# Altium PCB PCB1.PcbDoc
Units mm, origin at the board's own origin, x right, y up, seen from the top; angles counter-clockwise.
Board outline 100 x 70 mm, 2 copper layers (Top Layer, Bottom Layer); 90 components, 34 nets, 176 pads, 28 vias.
Unrouted connection lines stored in the file: 3.
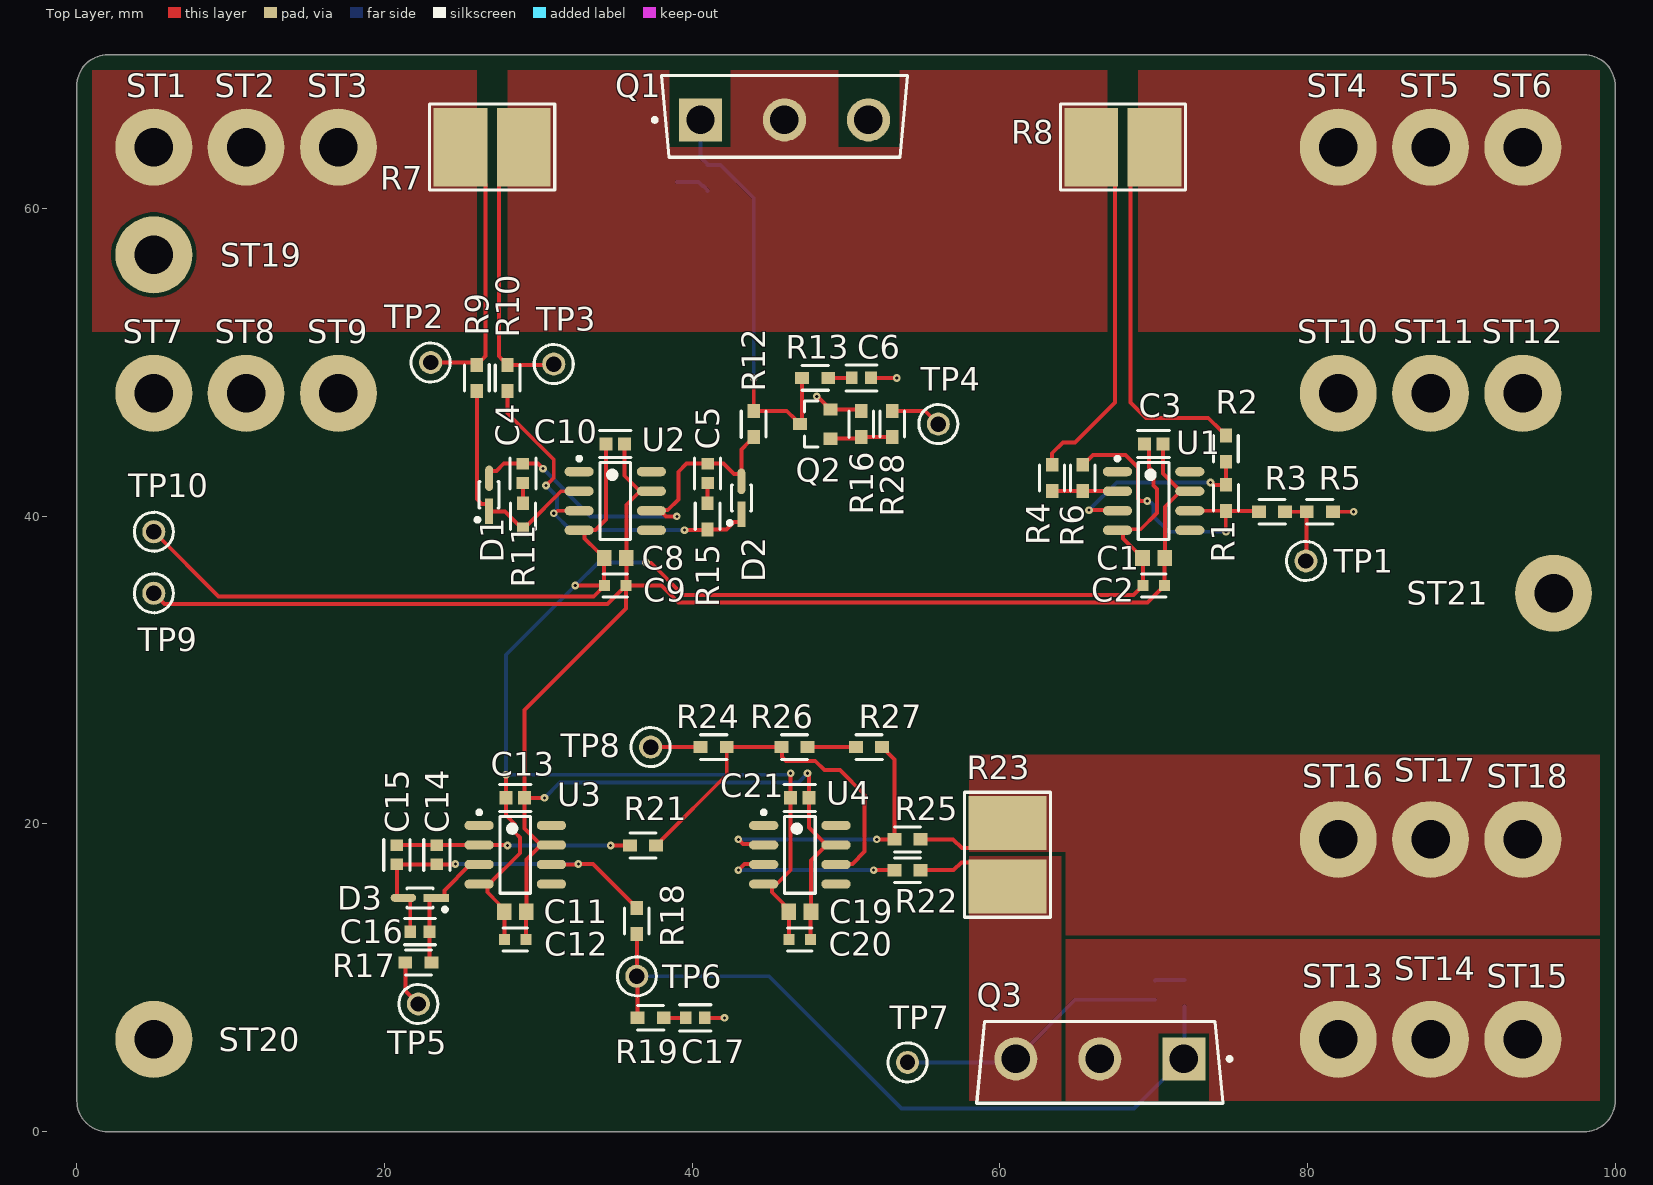
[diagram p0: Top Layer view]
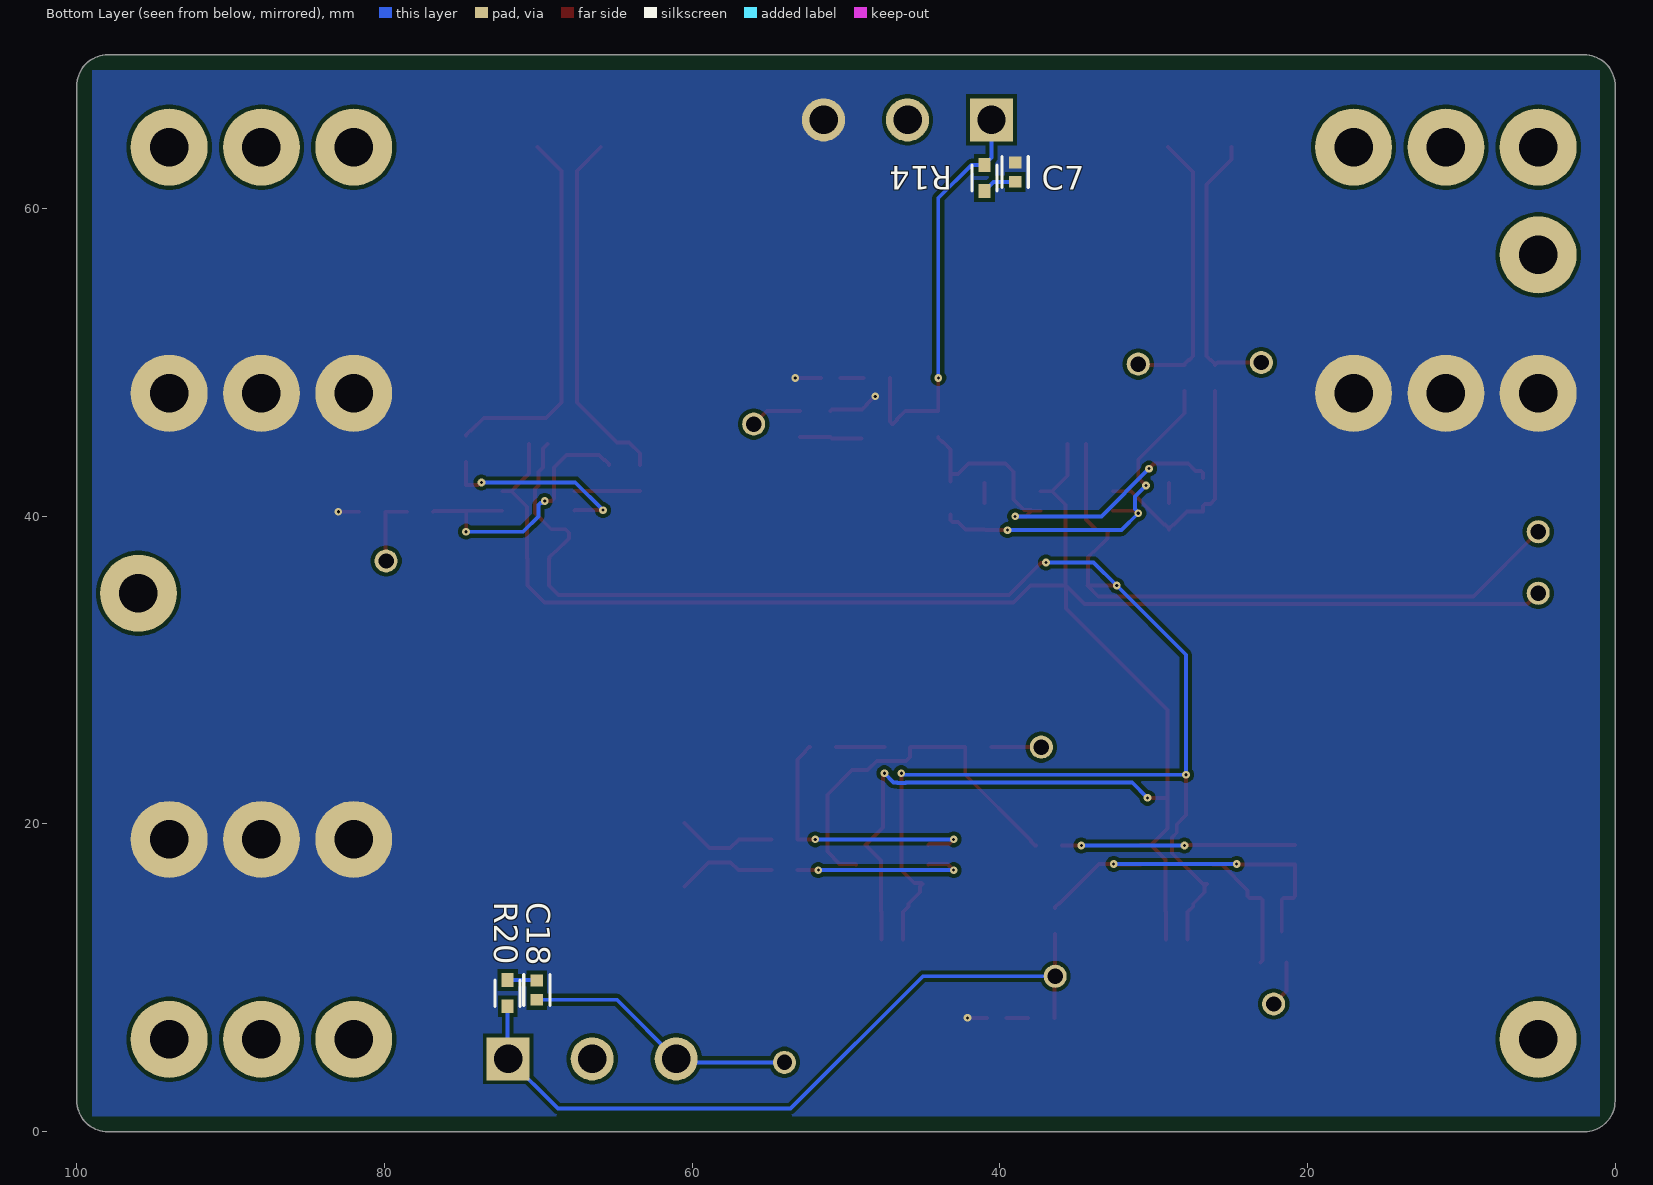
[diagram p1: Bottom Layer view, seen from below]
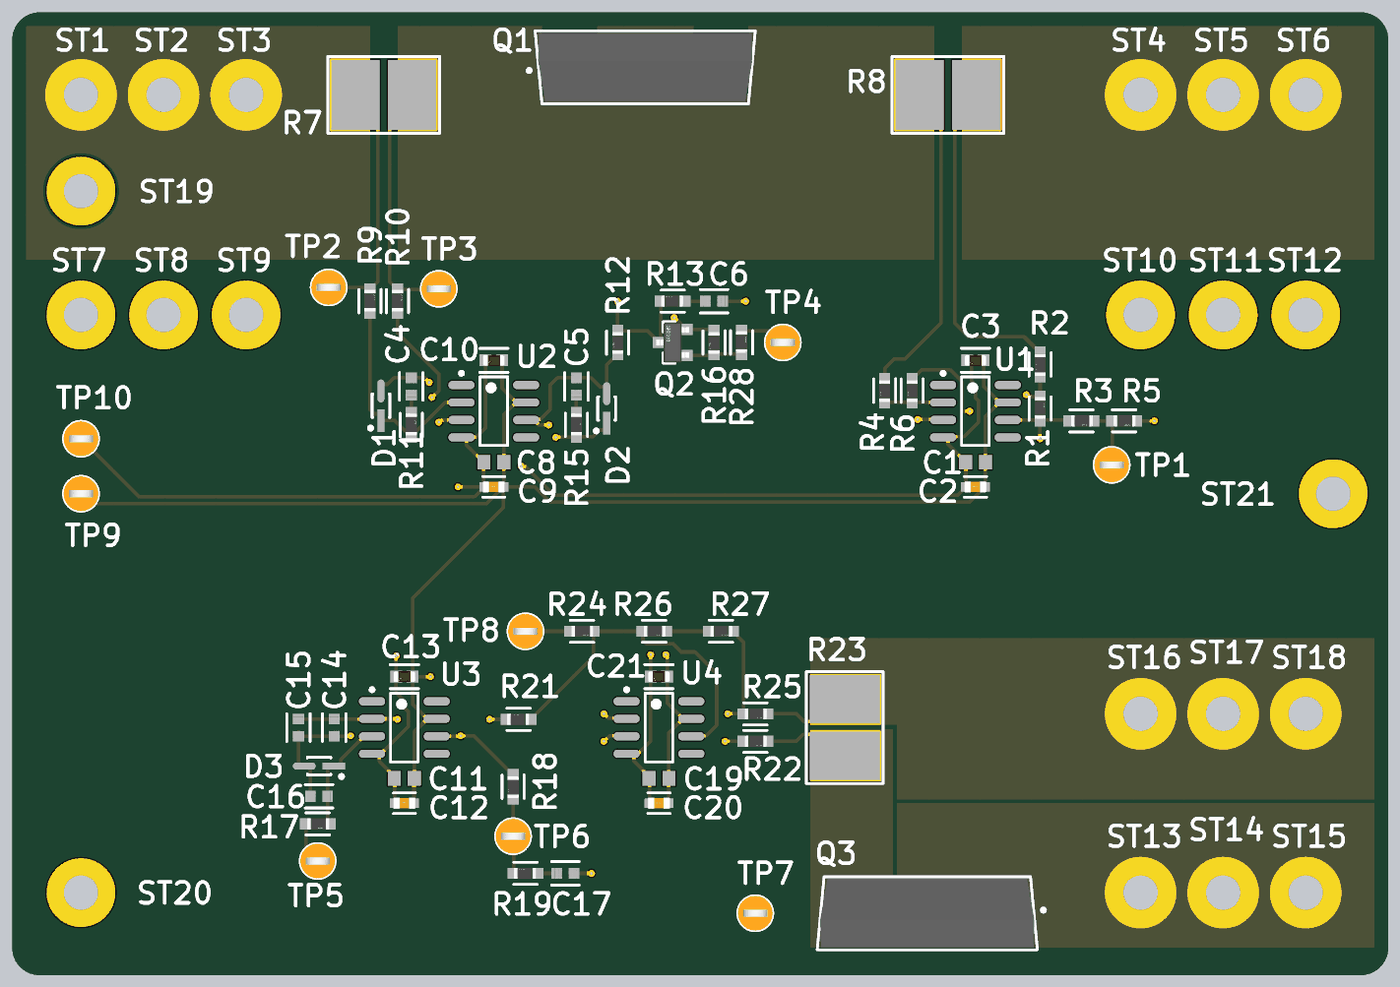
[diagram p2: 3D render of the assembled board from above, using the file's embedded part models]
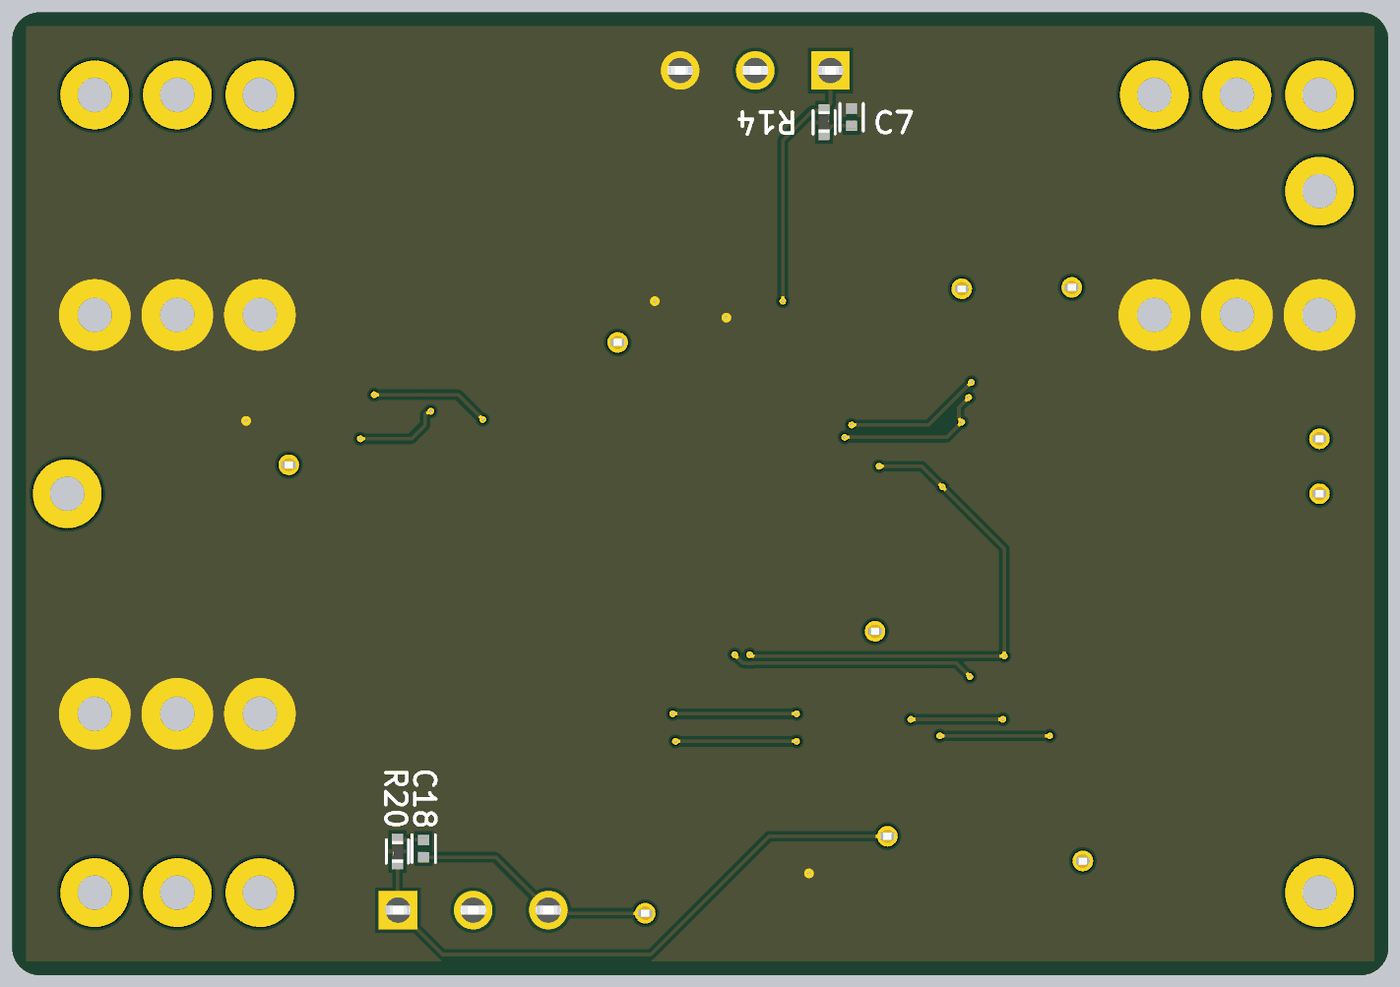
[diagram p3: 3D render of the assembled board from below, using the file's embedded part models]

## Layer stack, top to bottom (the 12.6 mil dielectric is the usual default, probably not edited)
Top Solder: solder mask 0.0102, Solder Resist, Dk 3.5
Top Layer: signal copper 0.0356
Dielectric 1: dielectric 0.32, FR-4, Dk 4.8
Bottom Layer: signal copper 0.0356
Bottom Solder: solder mask 0.0102, Solder Resist, Dk 3.5

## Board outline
2,0 98,0 ccw(c98,2) 100,2 100,68 ccw(c98,68) 98,70 2,70 ccw(c2,68) 0,68 0,2 ccw(c2,2)

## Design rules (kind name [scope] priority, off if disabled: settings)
Clearance [All] p1: gap=0.254 ignorepadtopadclearanceinfootprint=FALSE except(0: Arc-Hole Track-Hole SMDPad-Hole THPad-Hole Via-Hole Fill-Hole Poly-Hole Region-Hole Text-Hole)
PolygonConnect PolygonConnect_1 [All vs IsNamedPolygon('NONET_L01_P-001') Or IsNamedPolygon('NONET_L01_P-001') Or IsNamedPolygon('NONET_L01_P-001') Or IsNamedPolygon('NONET_L01_P-001') Or IsNamedPolygon('NONET_L01_P-001') Or IsNamedPolygon('NONET_L01_P-001') Or IsNamedPolygon('NONET_L01_P-001')] p1: connectstyle=Direct reliefconductorwidth=0.254 reliefentries=4 polygonreliefangle="90 Angle" airgapwidth=0.254
PolygonConnect [All] p2: connectstyle=Relief reliefconductorwidth=0.254 reliefentries=4 polygonreliefangle="90 Angle" airgapwidth=0.254
RoutingVias [All] p1: holewidth=0.2 width=0.5 viastyle="Through Hole" minholewidth=0.2 minwidth=0.5 maxholewidth=0.2 maxwidth=0.5
SilkToSilkClearance [All] p1: silktosilkclearance=0.15
SolderMaskExpansion [All] p1: expansion=0.102 istentingtop=FALSE
Width [All] p1: maxlimit=0.254 minlimit=0.254 preferedwidth=0.254
29 further rules are at their usual default settings.

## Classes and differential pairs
component class CV: C1 C2 C3 C4 C5 C6 C7 C8 C9 C10 D1 D2 Q1 Q2 R1 R2 R3 R4 R5 R6 R7 R8 R9 R10 R11 R12 R13 R14 R15 R16 R28 ST1 ST2 ST3 ST4 ST5 ST6 ST7 ST8 ST9 ST10 ST11 ST12 ST20 TP1 TP2 TP3 TP4 TP9 TP10 U1 U2
component class CC: C11 C12 C13 C14 C15 C16 C17 C18 C19 C20 C21 D3 Q3 R17 R18 R19 R20 R21 R22 R23 R24 R25 R26 R27 ST13 ST14 ST15 ST16 ST17 ST18 TP5 TP6 TP7 TP8 U3 U4

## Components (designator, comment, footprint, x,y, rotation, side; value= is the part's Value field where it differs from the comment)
C1 "CL10B104KB8NNNC" SAMS-C0603-2_M 70,37.3 r0 top
C2 "C1608X7R1H103M080AA" FP-C1608-080-0_1-MFG 70,35.5 r0 top
C3 "UMK107AB7105KA-T" FP-0603-L_1_6_0_15-W_0_8-IPC_C 70,44.7 r180 top
C4 "CL10B102KB8WPNC" FP-CL10-IPC_C 29,42.8 r90 top
C5 "CL10B102KB8WPNC" FP-CL10-IPC_C 41,42.8 r90 top
C6 "CL10B102KB8WPNC" FP-CL10-IPC_C 51,49 r180 top
C7 "CL10B102KB8WPNC" FP-CL10-IPC_C 39,62.373 r270 bottom
C8 "CL10B104KB8NNNC" SAMS-C0603-2_M 35,37.3 r0 top
C9 "C1608X7R1H103M080AA" FP-C1608-080-0_1-MFG 35,35.5 r0 top
C10 "UMK107AB7105KA-T" FP-0603-L_1_6_0_15-W_0_8-IPC_C 35,44.7 r180 top
C11 "CL10B104KB8NNNC" SAMS-C0603-2_M 28.5,14.3 r0 top
C12 "C1608X7R1H103M080AA" FP-C1608-080-0_1-MFG 28.5,12.5 r0 top
C13 "UMK107AB7105KA-T" FP-0603-L_1_6_0_15-W_0_8-IPC_C 28.5,21.7 r180 top
C14 "CL10B102KB8WPNC" FP-CL10-IPC_C 23.4,18 r90 top
C15 "CL10B102KB8WPNC" FP-CL10-IPC_C 20.8,18 r90 top
C16 "CL10B102KB8WPNC" FP-CL10-IPC_C 22.3,13 r0 top
C17 "CL10B102KB8WPNC" FP-CL10-IPC_C 40.2,7.4 r180 top
C18 "CL10B102KB8WPNC" FP-CL10-IPC_C 70.1,9.2 r90 bottom
C19 "CL10B104KB8NNNC" SAMS-C0603-2_M 47,14.3 r0 top
C20 "C1608X7R1H103M080AA" FP-C1608-080-0_1-MFG 47,12.5 r0 top
C21 "UMK107AB7105KA-T" FP-0603-L_1_6_0_15-W_0_8-IPC_C 46.998,21.7 r180 top
D1 "BAS316,115" FP-SOD323-IPC_A 26.8,41.4 r90 top
D2 "BAS316,115" FP-SOD323-IPC_A 43.2,41.2 r90 top
D3 "BAS316,115" FP-SOD323-IPC_A 22.3,15.2 r180 top
Q1 "IRFP250NPBF" FP-PG-TO247-3-MFG 46,66 r90 top
Q2 "2N7002-7-F" FP-SOT23-MFG 48,46 r180 top
Q3 "IRFP250NPBF" FP-PG-TO247-3-MFG 66.5,4.5 r270 top
R1 "RT0603FRE071KL" FP-RT0603-MFG 74.7,41.2 r90 top value=1KΩ
R2 "RT0603FRE071KL" FP-RT0603-MFG 74.7,44.4 r270 top value=1KΩ
R3 "RT0603FRE071KL" FP-RT0603-MFG 77.7,40.3 r0 top value=1KΩ
R4 "RT0603FRE071KL" FP-RT0603-MFG 63.4,42.5 r270 top value=1KΩ
R5 "RT0603FRE071KL" FP-RT0603-MFG 80.8,40.3 r0 top value=1KΩ
R6 "RT0603FRE071KL" FP-RT0603-MFG 65.4,42.5 r270 top value=1KΩ
R7 "WSHM2818R0200FEA" WSHM2818R0200FEA 27,64 r0 top value=0.02R
R8 "WSHM2818R0200FEA" WSHM2818R0200FEA 68,64 r0 top value=0.02R
R9 "RT0603FRE071KL" FP-RT0603-MFG 26,49 r90 top value=1KΩ
R10 "RT0603FRE071KL" FP-RT0603-MFG 28,49 r90 top value=1KΩ
R11 "RT0603FRE071KL" FP-RT0603-MFG 29,40 r90 top value=1KΩ
R12 "RT0603FRE07470RL" FP-RT0603-MFG 44,46 r270 top value=470Ω
R13 "RT0603FRE071KL" FP-RT0603-MFG 48,49 r180 top value=1KΩ
R14 "RT0603FRE071KL" FP-RT0603-MFG 41,62 r90 bottom value=1KΩ
R15 "RT0603FRE071KL" FP-RT0603-MFG 41,40 r90 top value=1KΩ
R16 "RT0603FRE071KL" FP-RT0603-MFG 51,46 r270 top value=1KΩ
R17 "RT0603FRE071KL" FP-RT0603-MFG 22.2,11 r0 top value=1KΩ
R18 "RT0603FRE071KL" FP-RT0603-MFG 36.4,13.7 r270 top value=1KΩ
R19 "RT0603FRE071KL" FP-RT0603-MFG 37.3,7.4 r180 top value=1KΩ
R20 "RT0603FRE071KL" FP-RT0603-MFG 72,9 r270 bottom value=1KΩ
R21 "RT0603FRE071KL" FP-RT0603-MFG 36.8,18.6 r180 top value=1KΩ
R22 "RT0603FRE071KL" FP-RT0603-MFG 54,17 r0 top value=1KΩ
R23 "WSHM2818R0200FEA" WSHM2818R0200FEA 60.5,18 r270 top value=0.02R
R24 "RT0603FRE071KL" FP-RT0603-MFG 41.4,25 r0 top value=1KΩ
R25 "RT0603FRE071KL" FP-RT0603-MFG 54,19 r0 top value=1KΩ
R26 "RT0603FRE071KL" FP-RT0603-MFG 46.65,25 r0 top value=1KΩ
R27 "RT0603FRE071KL" FP-RT0603-MFG 51.5,25 r0 top value=1KΩ
R28 "RT0603FRE071KL" FP-RT0603-MFG 53,46 r90 top value=1KΩ
ST1 "PTH-M2D5X5" PTH-M2D5X5 5,64 r0 top
ST2 "PTH-M2D5X5" PTH-M2D5X5 11,64 r0 top
ST3 "PTH-M2D5X5" PTH-M2D5X5 17,64 r0 top
ST4 "PTH-M2D5X5" PTH-M2D5X5 82,64 r0 top
ST5 "PTH-M2D5X5" PTH-M2D5X5 88,64 r0 top
ST6 "PTH-M2D5X5" PTH-M2D5X5 94,64 r0 top
ST7 "PTH-M2D5X5" PTH-M2D5X5 5,48 r0 top
ST8 "PTH-M2D5X5" PTH-M2D5X5 11,48 r0 top
ST9 "PTH-M2D5X5" PTH-M2D5X5 17,48 r0 top
ST10 "PTH-M2D5X5" PTH-M2D5X5 82,48 r0 top
ST11 "PTH-M2D5X5" PTH-M2D5X5 88,48 r0 top
ST12 "PTH-M2D5X5" PTH-M2D5X5 94,48 r0 top
ST13 "PTH-M2D5X5" PTH-M2D5X5 82,6 r0 top
ST14 "PTH-M2D5X5" PTH-M2D5X5 88,6 r0 top
ST15 "PTH-M2D5X5" PTH-M2D5X5 94,6 r0 top
ST16 "PTH-M2D5X5" PTH-M2D5X5 82,19 r0 top
ST17 "PTH-M2D5X5" PTH-M2D5X5 88,19 r0 top
ST18 "PTH-M2D5X5" PTH-M2D5X5 94,19 r0 top
ST19 "PTH-M2D5X5" PTH-M2D5X5 5,57 r0 top
ST20 "PTH-M2D5X5" PTH-M2D5X5 5,6 r0 top
ST21 "PTH-M2D5X5" PTH-M2D5X5 96,35 r0 top
TP1 "5003" KSTN-5003 79.9,37.1 r0 top
TP2 "5003" KSTN-5003 23,50 r0 top
TP3 "5003" KSTN-5003 31,49.9 r0 top
TP4 "5003" KSTN-5003 56,46 r0 top
TP5 "5003" KSTN-5003 22.2,8.3 r0 top
TP6 "5003" KSTN-5003 36.4,10.1 r0 top
TP7 "5003" KSTN-5003 54,4.5 r0 top
TP8 "5003" KSTN-5003 37.3,25 r0 top
TP9 "5003" KSTN-5003 5,35 r0 top
TP10 "5003" KSTN-5003 5,39 r180 top
U1 "LTC2050HVCS8#PBF" LT-S8-8_L 70,41 r0 top
U2 "LTC2050HVCS8#PBF" LT-S8-8_L 35,41 r0 top
U3 "LTC2050HVCS8#PBF" LT-S8-8_L 28.5,18 r0 top
U4 "LTC2050HVCS8#PBF" LT-S8-8_L 47,18 r0 top

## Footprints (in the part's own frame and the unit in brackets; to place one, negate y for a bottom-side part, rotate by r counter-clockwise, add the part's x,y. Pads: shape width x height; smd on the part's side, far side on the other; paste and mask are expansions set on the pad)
FP-0603-L_1_6_0_15-W_0_8-IPC_C [mm]
  rect 0.858x0.862 smd paste+0 mask+0: 1(-0.602,0) 2(0.602,0)
  silkscreen extent -1.03,-0.87 1.03,0.87, body extent -1.13,-0.58 1.13,0.58, height 0.25
FP-C1608-080-0_1-MFG [mm]
  rect 0.7x0.7 smd paste+0 mask+0: 1(-0.7,0) 2(0.7,0)
  silkscreen extent -0.8,-0.75 0.8,0.75, body extent -1.15,-0.55 1.15,0.55, height 0.25
FP-CL10-IPC_C [mm]
  rect 0.758x0.812 smd paste+0 mask+0: 1(-0.627,0) 2(0.627,0)
  silkscreen extent -1.01,-0.85 1.01,0.85, body extent -1.11,-0.55 1.11,0.55, height 0.25
FP-PG-TO247-3-MFG [mm]
  rect 2.8x2.8 hole 1.85 paste-1000 mask+0: 1(-0.228,5.46)
  round 2.8 hole 1.85 paste-1000 mask+0: 2(-0.228,0) 3(-0.228,-5.46)
  silkscreen extent -2.66,-8 2.66,8.56, body extent -2.76,-8.16 2.76,8.16, height 0.25
FP-RT0603-MFG [mm]
  rect 0.9x0.8 smd paste+0 mask+0: 1(-0.85,0) 2(0.85,0)
  silkscreen extent -0.85,-0.81 0.86,0.8, body extent -1.4,-0.55 1.4,0.55, height 0.25
FP-SOD323-IPC_A [mm]
  rect 1.655x0.516 smd paste+0 mask+0: 1(-1.075,0)
  rrect100% 1.655x0.516 smd paste+0 mask+0: 2(1.075,0)
  silkscreen extent -1.75,-0.65 0.85,0.88
FP-SOT23-MFG [mm]
  rect 0.9x0.8 smd paste+0 mask+0: 1(-1,0.95) 2(-1,-0.95) 3(1,0)
  silkscreen extent -0.18,-1.5 0.7,1.5, body extent -1.55,-1.6 1.55,1.6, height 0.25
KSTN-5003 [mm] "Test Point, Through Hole, Dia 2.54mm"
  round 1.5 hole 1: 1(0,0)
  silkscreen extent -1.27,-1.27 1.27,1.27, body extent -1.27,-1.27 1.27,1.27, height 4.57
LT-S8-8_L [mm] "SOIC, 8-Leads, Body 4.9x3.9mm, Pitch 1.27mm, IPC High Density"
  oval 1.9x0.6 smd: 1(-2.35,1.905) 2(-2.35,0.635) 3(-2.35,-0.635) 4(-2.35,-1.905) 5(2.35,-1.905) 6(2.35,-0.635) 7(2.35,0.635) 8(2.35,1.905)
  silkscreen extent -2.47,-2.5 1,2.88, body extent -2,-2.5 2,2.5, height 1.76
PTH-M2D5X5 [mm]
  round 5 hole 2.5: 1(0,0)
SAMS-C0603-2_M [mm] "Chip Capacitor, 2-Leads, Body 1.70x0.90mm, IPC Low Density"
  rect 0.95x1.05 smd: 1(-0.725,0) 2(0.725,0)
  body extent -0.85,-0.45 0.85,0.45, height 0.9
WSHM2818R0200FEA [mm]
  rect 3.5x5.1 smd: 1(-2.055,0) 2(2.055,0)
  silkscreen extent -4.06,-2.79 4.06,2.79

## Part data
C1 C8 C11 C19: library part CMP-2000-05332-1, "Multi-layer Ceramic Capacitor, -55 to 125 degC, 2-Pin SMD (0603), RoHS, Tape and Reel", Capacitance=0.1µF, Case Size/Dimension=0603, Dielectric=X7R, Manufacturer="Samsung Electro-Mechanics", Rated Voltage=50V, Tolerance (%)=±10%
C2 C9 C12 C20: library part CMP-08246-006703-1, "Multilayer Ceramic Capacitors 10nF ±20% 50V X7R SMD 0603", Capacitance=10nF, Case Code (Imperial)=0603, Case Code (Metric)=1608, Dielectric=X7R, Dielectric Material=Ceramic, Max Operating Temperature=125°C, Min Operating Temperature=-55°C, Package Quantity=1, Tolerance=20%, Voltage Rating=50V
C3 C10 C13 C21: library part CMP-2000-07531-4, "Ceramic Capacitor General Use 1uF ±10% 50V X7R 0603", Capacitance=1uF, Case Code (Imperial)=0603, Case Code (Metric)=1608, Dielectric=X7R, Max Operating Temperature=125°C, Min Operating Temperature=-55°C, Package Quantity=1, Tolerance=10%, Voltage Rating=50V
C4 C5 C6 C7 C14 C15 C16 C17 C18: library part CMP-13271-004548-1, "Cap Ceramic 1nF 50V X7R ±10% Pad SMD 0603 +125°C T/R", Capacitance=1nF, Case Code (Imperial)=0603, Case Code (Metric)=1608, Max Operating Temperature=125°C, Min Operating Temperature=-55°C, Ratings=AEC-Q200, Tolerance=10%, Voltage Rating=50V
D1 D2 D3: library part CMP-14399-000012-1, "DIODE GEN PURP 100V 250MA SOD323"
Q1 Q3: library part CMP-32901-000198-1, "MOSFET N-CH 200V 30A TO-247AC", Case/Package=TO-247, Continuous Drain Current (ID)=30A, Drain to Source Breakdown Voltage=200V, Drain to Source Resistance=75mR, Gate to Source Voltage (Vgs)=20V, Input Capacitance=2.159nF, Max Operating Temperature=175°C, Max Power Dissipation=214W, Min Operating Temperature=-55°C
Q2: library part CMP-2000-04929-2, "MOSFET N-CH 60V 115MA SOT23-3", Case/Package=SOT-23, Continuous Drain Current (ID)=115mA, Drain to Source Breakdown Voltage=70V, Drain to Source Resistance=7.5R, Drain to Source Voltage (Vdss)=60V, Gate to Source Voltage (Vgs)=20V, Input Capacitance=50pF, Max Operating Temperature=150°C, Max Power Dissipation=300mW, Min Operating Temperature=-55°C, Package Quantity=3000, Power Dissipation=540mW, Threshold Voltage=2.5V
R1 R6: library part CMP-03412-005349-1, "RES SMD 1K OHM 1% 1/10W 0603 Je tuspatny datasheet!!!", Case Code (Imperial)=0603, Case Code (Metric)=1608, Manufacturer=Yageo, Manufacturer Part Number=RT0603FRE0710KL, Max Operating Temperature=125°C, Max Power Dissipation=100mW, Min Operating Temperature=-55°C, Package=RT0603, Package Quantity=5000, Power Rating=0.1W, Resistance=1K81, Resistance Tolerance=1%, Resistor Type="Thin Film", Supplier Part Number 1=2693905, Temperature="-55°C to +155°C", Temperature Coefficient="50 ppm/°C", Temperature Range High=+155°C, Tolerance=0.01, Voltage Rating=75V
R2 R4: library part CMP-03412-005349-1, "RES SMD 1K OHM 1% 1/10W 0603 Je tuspatny datasheet!!!", Case Code (Imperial)=0603, Case Code (Metric)=1608, Manufacturer=Yageo, Manufacturer Part Number=RT0603FRE0710KL, Max Operating Temperature=125°C, Max Power Dissipation=100mW, Min Operating Temperature=-55°C, Package=RT0603, Package Quantity=5000, Power Rating=0.1W, Resistance=82R, Resistance Tolerance=1%, Resistor Type="Thin Film", Supplier Part Number 1=2693905, Temperature="-55°C to +155°C", Temperature Coefficient="50 ppm/°C", Temperature Range High=+155°C, Tolerance=0.01, Voltage Rating=75V
R3 R9 R10 R11 R13 R14 R15 R16 R19 R20 R28: library part CMP-03412-005349-1, "RES SMD 1K OHM 1% 1/10W 0603 Je tuspatny datasheet!!!", Case Code (Imperial)=0603, Case Code (Metric)=1608, Manufacturer=Yageo, Manufacturer Part Number=RT0603FRE0710KL, Max Operating Temperature=125°C, Max Power Dissipation=100mW, Min Operating Temperature=-55°C, Package=RT0603, Package Quantity=5000, Power Rating=0.1W, Resistance=1KΩ, Resistance Tolerance=1%, Resistor Type="Thin Film", Supplier Part Number 1=2693905, Temperature="-55°C to +155°C", Temperature Coefficient="50 ppm/°C", Temperature Range High=+155°C, Tolerance=0.01, Voltage Rating=75V
R5 R26: library part CMP-03412-005349-1, "RES SMD 1K OHM 1% 1/10W 0603 Je tuspatny datasheet!!!", Case Code (Imperial)=0603, Case Code (Metric)=1608, Manufacturer=Yageo, Manufacturer Part Number=RT0603FRE0710KL, Max Operating Temperature=125°C, Max Power Dissipation=100mW, Min Operating Temperature=-55°C, Package=RT0603, Package Quantity=5000, Power Rating=0.1W, Resistance=(-), Resistance Tolerance=1%, Resistor Type="Thin Film", Supplier Part Number 1=2693905, Temperature="-55°C to +155°C", Temperature Coefficient="50 ppm/°C", Temperature Range High=+155°C, Tolerance=0.01, Voltage Rating=75V
R7 R8 R23: "Rezistory ke snímání proudu - SMD .02ohms 7watt 1%", Power=7W
R12: library part CMP-03412-035774-1, "RES 470 OHM 1/10W 1% SMD 0603", Manufacturer=Yageo, Package=RT0603, Power Rating=0.1W, Resistance=470Ω, Temperature="-55°C to +155°C", Temperature Coefficient="50 ppm/°C", Temperature Range High=+155°C, Temperature Range Low=-55°C, Tolerance=0.01, Voltage Rating=75V
R17 R18 R21 R22 R24: library part CMP-03412-005349-1, "RES SMD 1K OHM 1% 1/10W 0603 Je tuspatny datasheet!!!", Case Code (Imperial)=0603, Case Code (Metric)=1608, Manufacturer=Yageo, Manufacturer Part Number=RT0603FRE0710KL, Max Operating Temperature=125°C, Max Power Dissipation=100mW, Min Operating Temperature=-55°C, Package=RT0603, Package Quantity=5000, Power Rating=0.1W, Resistance=10KΩ, Resistance Tolerance=1%, Resistor Type="Thin Film", Supplier Part Number 1=2693905, Temperature="-55°C to +155°C", Temperature Coefficient="50 ppm/°C", Temperature Range High=+155°C, Tolerance=0.01, Voltage Rating=75V
R25 R27: library part CMP-03412-005349-1, "RES SMD 1K OHM 1% 1/10W 0603 Je tuspatny datasheet!!!", Case Code (Imperial)=0603, Case Code (Metric)=1608, Manufacturer=Yageo, Manufacturer Part Number=RT0603FRE0710KL, Max Operating Temperature=125°C, Max Power Dissipation=100mW, Min Operating Temperature=-55°C, Package=RT0603, Package Quantity=5000, Power Rating=0.1W, Resistance=50KΩ, Resistance Tolerance=1%, Resistor Type="Thin Film", Supplier Part Number 1=2693905, Temperature="-55°C to +155°C", Temperature Coefficient="50 ppm/°C", Temperature Range High=+155°C, Tolerance=0.01, Voltage Rating=75V
ST1 ST2 ST3 ST4 ST5 ST6 ST7 ST8 ST9 ST10 ST11 ST12 ST13 ST14 ST15 ST16 ST17 ST18 ST19 ST20 ST21: library part CMP-00028-00004-1, "M2 PTH (2.5mm), 5mm pad"
TP1 TP2 TP3 TP4 TP5 TP6 TP7 TP8 TP9 TP10: library part CMP-002-00037-1, "Test Point, Orange, Height 4.6 mm, Tail Length 3 mm, 1-Pin THD, RoHS", Colour=Orange, Manufacturer=Keystone, Package Description="1-Pin Through Hole Device, Dia 2.54 mm", Package Quantity=10
U1 U2 U3 U4: library part CMP-0359-03372-2, "Single Channel, Zero-Drift Operational Amplifier, 3 MHz Typical GBW, 2 V/us Typical SR, 2.7 to 11 V, 8-Pin SOIC (S8-8), Commercial, Pb-Free", Linear Technology Part Number=LTC2050HV, Manufacturer="Linear Technology"

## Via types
v1: diameter 0.5, hole 0.2, Top Layer to Bottom Layer, 28 vias

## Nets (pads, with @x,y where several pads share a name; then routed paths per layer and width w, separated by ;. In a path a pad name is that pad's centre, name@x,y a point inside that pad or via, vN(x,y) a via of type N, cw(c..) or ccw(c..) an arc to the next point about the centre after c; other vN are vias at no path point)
+5: C1.2 C2.2 C3.1 C8.2 C9.2 C10.1 C11.2 C12.2 C13.1 C19.2 C20.2 C21.1 TP9.1 U1.7 U2.7 U3.7 U4.7 | length 146.9
  Top Layer w0.254: TP9.1 5.708,34.292 34.492,34.292 C9.2 ; C12.2 29.2,14.275 C11.2 29.225,17.695 U3.7@30.165,18.635 ; v1(30.4,21.7) C13.1 ; U3.7 U3.7@30.165,18.635 ; C10.1 35.602,42.639 U2.7@36.606,41.635 ; U2.7 U2.7@36.606,41.635 ; v1(47.5,23.3) 47.5,23.233 47.6,23.133 C21.1 47.6,19.77 48.735,18.635 47.725,17.625 C19.2 47.7,14.275 C20.2 ; C3.1 70.602,42.776 71.378,42 U1.7@71.743,41.635 ; U1.7 U1.7@71.743,41.635 ; C13.1 29.102,19.698 U3.7@30.165,18.635 ; C13.1 29.102,27.402 35.7,34 C9.2 ; C9.2 38,35.5 39.108,34.392 68.91,34.392 68.918,34.4 69.6,34.4 C2.2 70.7,37.275 C1.2 70.725,40.625 71.735,41.635 U1.7@71.743,41.635 ; C9.2 35.725,35.525 C8.2 35.725,40.754 U2.7@36.606,41.635
  Bottom Layer w0.254: v1(30.4,21.7) 31.392,22.692 46.116,22.692 46.139,22.669 46.661,22.669 46.692,22.7 46.9,22.7 v1(47.5,23.3)
-5: C1.1 C2.1 C3.2 C8.1 C9.1 C10.2 C11.1 C12.1 C13.2 C19.1 C20.1 C21.2 TP10.1 U1.4 U2.4 U3.4 U4.4 | length 152.4
  Top Layer w0.254: TP10.1 9.2,34.8 33.6,34.8 C9.1 ; C12.1 27.8,14.275 C11.1 27.427,14.648 27.427,14.818 26.682,15.563 26.682,15.935 26.522,16.095 26.795,16.095 28.8,18.1 28.8,19.129 28.5,19.429 28.5,19.972 27.898,20.574 C13.2 27.9,21.702 v1(27.9,23.2) ; v1(32.4,35.5) C9.1 ; C10.2 34.398,39.798 33.725,39.125 32.68,39.125 U2.4 32.852,39.095 33.012,38.935 33.012,38.563 33.877,37.698 33.927,37.698 34.275,37.35 C8.1 34.275,35.525 C9.1 ; v1(37,37) 37.042,36.958 37.342,36.958 39.4,34.9 68.7,34.9 C2.1 69.3,37.275 C1.1 69.275,37.35 68.927,37.698 68.877,37.698 68.012,38.563 68.012,38.935 68.238,39.161 69.161,39.161 70.217,40.217 70.217,41.783 70,42 70,42.885 69.7,43.185 69.7,44.247 69.7,44.398 C3.2 ; C20.1 46.3,14.275 C19.1 45.927,14.648 45.927,14.818 45.182,15.563 45.182,15.935 45.022,16.095 45.089,16.161 45.561,16.161 46.396,16.996 C21.2 46.4,21.704 v1(46.4,23.3)
  Bottom Layer w0.254: v1(37,37) 33.9,37 v1(32.4,35.5) 27.9,31 v1(27.9,23.2) 46.233,23.2 46.333,23.3 v1(46.4,23.3)
GND: C6.1 C7.1 C17.1 Q1.3 Q2.2 R5.2 R16.1 R23.1 R25.2 ST7.1 ST8.1 ST9.1 ST10.1 ST11.1 ST12.1 ST16.1 ST17.1 ST18.1 | length 14.2
  Top Layer w0.254: C17.1 v1(42.1,7.4) ; v1(48.1,47.8) 48.15,47.8 48.677,47.273 48.677,47.223 48.95,46.95 Q2.2 50.9,46.95 R16.1 ; C6.1 v1(53.3,49) ; R25.2 56.964,19 57.532,18.432 58.877,18.432 R23.1 ; R5.2 v1(83,40.3)
NetC4_1: C4.1 R11.2 | length 1.3
  Top Layer w0.254: R11.2 C4.1
NetC4_2: C4.2 C5.2 D1.2 D2.2 R12.2 U2.6 | length 27.2
  Top Layer w0.254: D1.2 26.8,42.837 26.921,42.958 27.283,42.958 27.752,43.427 C4.2 29.973,43.427 v1(30.3,43.1) ; U2.6 37.635,40.365 U2.6@37.965,40.365 ; v1(39,40) 38.298,40 37.933,40.365 37.978,40.41 38.41,40.41 39.1,41.1 39.1,42.9 39.627,43.427 C5.2 42.048,43.427 42.717,42.758 43.079,42.758 D2.2@43.2,42.637 ; D2.2 D2.2@43.2,42.637 ; R12.2 44,45.1 43.727,44.827 43.677,44.827 43.2,44.35 D2.2@43.2,42.637
  Bottom Layer w0.254: v1(30.3,43.1) 33.4,40 v1(39,40)
NetC5_1: C5.1 R15.2 | length 1.3
  Top Layer w0.254: R15.2 C5.1
NetC6_2: C6.2 R13.1 | length 1.5
  Top Layer w0.254: R13.1 C6.2
NetC7_2: C7.2 R14.1 | length 2.3
  Bottom Layer w0.254: C7.2 40.404,61.746 40.677,61.473 40.727,61.473 41,61.2 R14.1
NetC14_1: C14.1 C15.1 C16.1 D3.2 R18.1 U3.6 | length 23.7
  Top Layer w0.254: C16.1 21.673,15.079 21.552,15.2 D3.2 20.921,15.2 20.8,15.321 C15.1 C14.1 24.573,17.373 v1(24.6,17.4) ; U3.6 32.565,17.365 v1(32.6,17.4) 33.55,17.4 36.077,14.873 36.127,14.873 36.4,14.6 R18.1
  Bottom Layer w0.254: v1(24.6,17.4) v1(32.6,17.4)
NetC14_2: C14.2 C15.2 R21.2 U3.2 | length 15.2
  Top Layer w0.254: C15.2 C14.2 26.142,18.627 U3.2 27.965,18.635 v1(28,18.6) ; v1(34.7,18.6) R21.2
  Bottom Layer w0.254: v1(28,18.6) v1(34.7,18.6)
NetC16_2: C16.2 D3.1 R17.2 U3.3 | length 8.5
  Top Layer w0.254: R17.2 22.927,11.123 C16.2 22.927,15.069 23.058,15.2 D3.1 23.759,15.2 23.89,15.331 23.89,15.69 25.565,17.365 U3.3
NetC17_2: C17.2 R19.1 | length 1.4
  Top Layer w0.254: R19.1 C17.2
NetC18_1: C18.1 Q3.3 R22.2 R23.2 TP7.1 | length 24.3
  Top Layer w0.254: R22.2 57,17 57.5,17.5 58.945,17.5 R23.2
  Bottom Layer w0.254: TP7.1 60.812,4.5 Q3.3 64.886,8.573 C18.1
NetC18_2: C18.2 R20.1 | length 1.9
  Bottom Layer w0.254: C18.2 70.123,9.85 R20.1
NetD1_1: D1.1 R9.1 R11.1 U2.2 | length 15.8
  Top Layer w0.254: R9.1 26,41.125 26.31,40.815 26.669,40.815 26.8,40.684 D1.1 27.825,40.325 28.677,39.473 28.727,39.473 R11.1@29,39.2 ; U2.2 31.485,41.635 29.323,39.473 29.273,39.473 R11.1@29,39.2 ; R11.1@29,39.2 R11.1 R11.1@29,39.2
NetD2_1: D2.1 R10.1 R15.1 U2.3 | length 24.8
  Top Layer w0.254: R10.1 28,46.7 31,43.7 31,42.5 v1(30.5,42) ; v1(31,40.2) 31.067,40.2 31.232,40.365 U2.3 ; v1(39.5,39.1) 40.95,39.1 R15.1 42.225,39.15 42.71,39.634 43.069,39.634 43.2,39.765 D2.1
  Bottom Layer w0.254: v1(30.5,42) 31.2,41.3 31.2,40.467 31,40.267 v1(31,40.2) 32.1,39.1 v1(39.5,39.1)
NetQ1_1: Q1.1 Q2.3 R12.1 R13.2 R14.2 | length 27.3
  Top Layer w0.254: v1(44,49) R12.1 46.15,46.85 46.677,46.323 46.677,46.273 46.95,46 Q2.3 47.15,46.15 R13.2
  Bottom Layer w0.254: Q1.1 40.54,63.322 40.689,63.173 40.727,63.173 41,62.9 R14.2 41.85,62.85 44,60.7 v1(44,49)
NetQ1_2: Q1.2 R4.1 R7.2 R8.1 R10.2 TP3.1 | length 41.6
  Top Layer w0.254: R7.2 27.44,62.385 27.44,50.41 27.677,50.173 27.727,50.173 28,49.9 R10.2 30.95,49.85 TP3.1 ; R4.1 63.4,44.1 64.1,44.8 64.9,44.8 67.5,47.4 67.5,62.445 R8.1
NetQ2_1: Q2.1 R16.2 R28.1 | length 4
  Top Layer w0.254: Q2.1 50.9,45.05 R16.2 R28.1
NetQ3_1: Q3.1 R18.2 R19.2 R20.2 TP6.1 | length 49.4
  Top Layer w0.254: R18.2 TP6.1 36.45,10.05 R19.2
  Bottom Layer w0.254: TP6.1 45,10.1 53.6,1.5 68.732,1.5 Q3.1 72,4.768 R20.2
NetQ3_2: Q3.2 ST13.1 ST14.1 ST15.1
NetR1_1: R1.1 R3.1 R6.1 U1.6 | length 19.2
  Top Layer w0.254: R6.1 65.4,43.4 65.673,43.673 65.723,43.673 66.05,44 68.168,44 68.981,43.187 68.981,42.15 68.981,41.149 69.13,41 v1(69.586,41) ; U1.6 74.685,40.365 74.685,39.015 v1(74.7,39) ; R1.1 76.8,40.35 R3.1
  Bottom Layer w0.254: v1(69.586,41) 69.653,41 69.776,40.877 69.851,40.877 70,40.728 70,40 71,39 v1(74.7,39)
NetR1_2: R1.2 R2.2 U1.3 | length 13.1
  Top Layer w0.254: v1(65.8,40.4) 67.615,40.4 U1.3 ; v1(73.7,42.2) 73.767,42.2 73.917,42.05 R1.2 R2.2
  Bottom Layer w0.254: v1(65.8,40.4) 67.6,42.2 v1(73.7,42.2)
NetR2_1: R2.1 R8.2 ST4.1 ST5.1 ST6.1 | length 24.4
  Top Layer w0.254: R8.2 68.5,62.445 68.5,47.4 69.5,46.4 73.55,46.4 74.377,45.573 74.427,45.573 74.7,45.3 R2.1
NetR3_2: R3.2 R5.1 TP1.1 | length 4.6
  Top Layer w0.254: R3.2 R5.1 79.95,37.15 TP1.1
NetR4_2: R4.2 R6.2 U1.2 | length 4.3
  Top Layer w0.254: R4.2 R6.2 67.635,41.65 U1.2
NetR7_1: R7.1 R9.2 ST1.1 ST2.1 ST3.1 TP2.1 | length 18.1
  Top Layer w0.254: TP2.1 25.85,50 R9.2 26,49.9 26.273,50.173 26.323,50.173 26.568,50.418 26.568,61.577 24.945,63.2 R7.1
NetR17_1: R17.1 TP5.1 | length 3.1
  Top Layer w0.254: R17.1 21.35,9.15 TP5.1
NetR21_1: R21.1 R24.2 R26.1 U4.6 | length 24.8
  Top Layer w0.254: R21.1 37.7,18.6 37.973,18.873 37.973,18.923 42.25,23.2 R24.2 R26.1 45.832,24.968 45.832,24.368 46.1,24.1 48,24.1 48.6,23.5 49.6,23.5 51.2,21.9 51.2,18.2 50.41,17.41 49.395,17.41 U4.6
NetR22_1: R22.1 U4.3 | length 12
  Top Layer w0.254: v1(43,17) 43.4,17.4 44.615,17.4 U4.3 ; v1(51.8,17) R22.1
  Bottom Layer w0.254: v1(43,17) v1(51.8,17)
NetR24_1: R24.1 TP8.1 | length 3.3
  Top Layer w0.254: TP8.1 R24.1
NetR25_1: R25.1 R27.2 U4.2 | length 18.3
  Top Layer w0.254: v1(43,19) 43.3,18.7 44.585,18.7 U4.2 ; v1(52,19) R25.1 53.15,24.2 52.673,24.677 52.673,24.727 52.4,25 R27.2
  Bottom Layer w0.254: v1(43,19) v1(52,19)
NetR26_2: R26.2 R27.1 | length 3.2
  Top Layer w0.254: R26.2 R27.1
NetR28_2: R28.2 TP4.1 | length 3.4
  Top Layer w0.254: R28.2 55.15,46.85 TP4.1
pads on no net: ST19.1 ST20.1 ST21.1 U1.1 U1.5 U1.8 U2.1 U2.5 U2.8 U3.1 U3.5 U3.8 U4.1 U4.5 U4.8

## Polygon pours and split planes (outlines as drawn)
GND on Top Layer "NONET_L01_P-001" (solid, pour order 8): 58,18.2 64.3,18.2 64.3,12.75 99,12.75 99,24.5 58,24.5
NetQ3_2 on Top Layer "NONET_L01_P-001" (solid, pour order 7): 99,2 99,12.5 64.3,12.5 64.3,2 70.3,2 70.3,6.4 73.6,6.4 73.6,2
NetC18_1 on Top Layer "NONET_L01_P-001" (solid, pour order 6): 58,17.9 64,17.9 64,2 58,2
NetR2_1 on Top Layer "NONET_L01_P-001" (solid, pour order 3): 69,69 99,69 99,52 69,52
NetR7_1 on Top Layer "NONET_L01_P-001" (solid, pour order 2): 26,69 26,52 1,52 1,69
NetQ1_2 on Top Layer "NONET_L01_P-001" (solid, pour order 0): 28,69 28,52 67,52 67,69 53.5,69 53.5,64 49.5,64 49.5,69 42.5,69 42.5,64 38.5,64 38.5,69
GND on Bottom Layer "NONET_L01_P-001" (solid, pour order 1): 1,69 1,1 99,1 99,69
